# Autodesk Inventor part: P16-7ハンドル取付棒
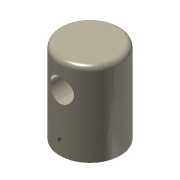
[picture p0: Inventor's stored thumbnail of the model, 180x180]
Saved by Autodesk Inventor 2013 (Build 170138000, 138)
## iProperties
Created: 2008-07
Part Number: P16-7ハンドル取付棒
Document SubType Name: Modeling
Designer: y-shimohigashi
Density: 1 g/cm^3
Material: 一般
Author: y-shimohigashi
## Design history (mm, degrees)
sketch "スケッチ1"
  geometry: C1 r 18 at (0, 0); 1 further point
  constraints: 1 centre point, 1 coincident
  dimensions: "d0" = 36 diameter of C1
extrude "押し出し1" new body sketch "スケッチ1" distance "d1" = 50; taper "d2" = 0 deg
sketch "スケッチ2"
  geometry: L1 (0, -10)-(0, 60) reference; L2 (-18, 50)-(18, 50) reference; C1 r 7 at (0, 34)
  constraints: 1 centre point, 1 point on line
  dimensions: "d3" = 14 diameter of C1; "d4" = 16 distance from line of L2 C1.centre
extrude "押し出し2" cut sketch "スケッチ2" stored distance "d5" = 50; taper "d6" = 0 deg
sketch "スケッチ3"
  geometry: L1 (0, -10)-(0, 60) reference; L2 (-18, 0)-(18, 0) reference; C1 r 1.5 at (0, 8)
  constraints: 1 centre point, 1 point on line
  dimensions: "d7" = 3 diameter of C1; "d8" = 8 distance from line of L2 C1.centre
extrude "押し出し3" cut sketch "スケッチ3" stored distance "d9" = 50; taper "d10" = 0 deg
feature "ねじ1" dims "d11" = 10, "d12" = 0
fillet "フィレット1" dims "d13" = 3
sketch "スケッチ4"
  geometry: L1 (3.536, -3.536)-(-3.536, -3.536); L2 (-3.536, -3.536)-(-3.536, 3.536); L3 (-3.536, 3.536)-(3.536, 3.536); L4 (3.536, 3.536)-(3.536, -3.536); L5 (3.536, 3.536)-(-3.536, -3.536); 2 further points
  constraints: 10 end point, 2 parallel, 2 perpendicular, 1 coincident, 1 horizontal, 1 midpoint
  dimensions: "d14" = 10 distance of L3.end L1.end
extrude "押し出し4" cut sketch "スケッチ4" stored distance "d15" = 50; taper "d16" = 0 deg
node "ソリッド1"
node "ソリッド ボディ"
node "サーフェス ボディ"
